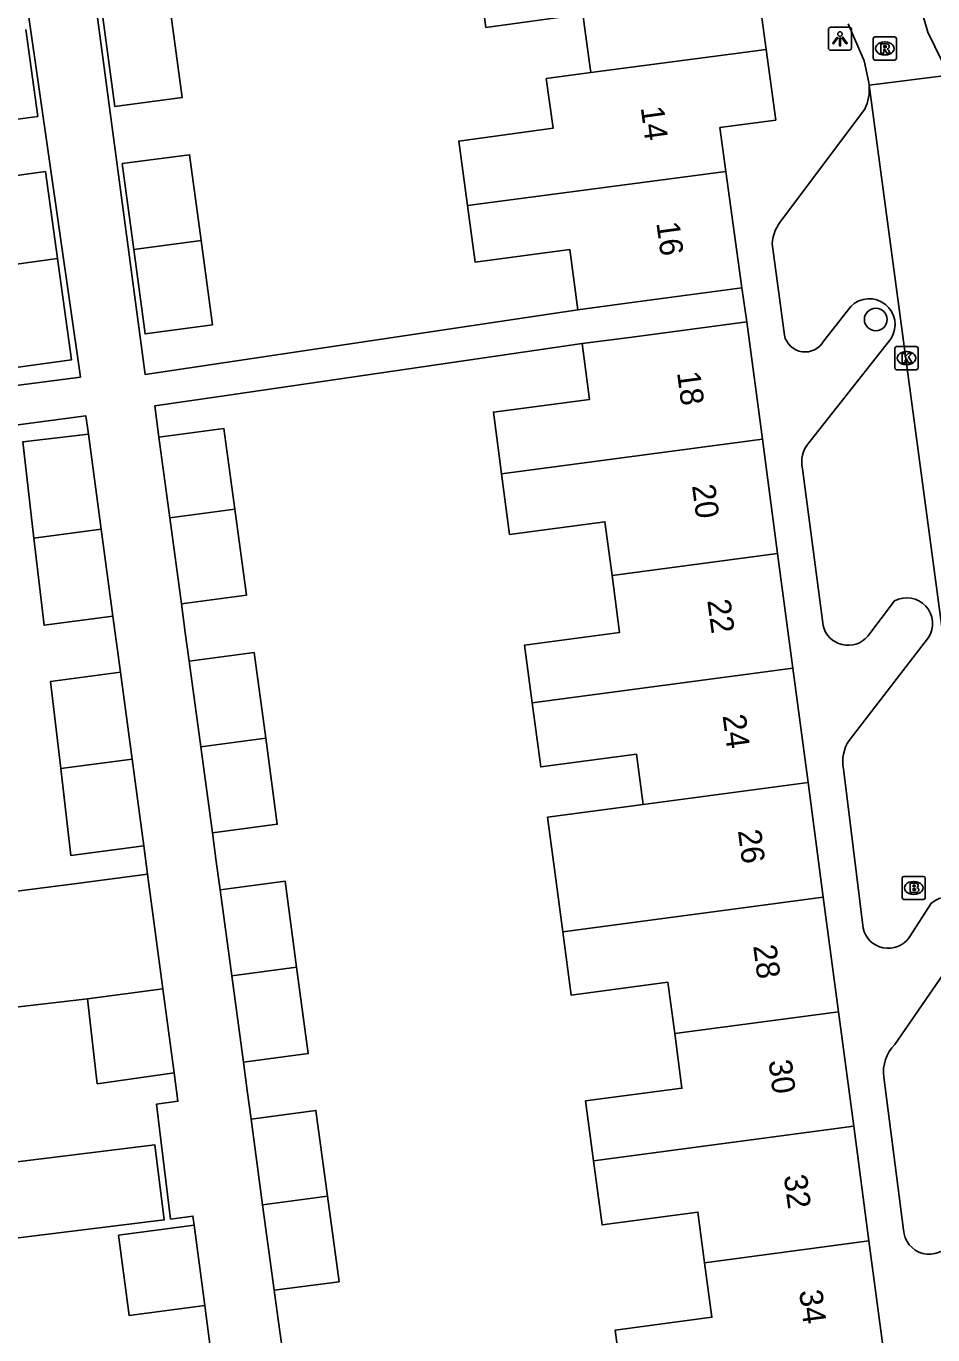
# Model space of a CAD drawing. Extents: x 163150 to 163546, y 380933 to 381635.
# Drawn here: x 163292.5 to 163331.7, y 381373.6 to 381430.1 of the extents above; entities that cross this region are included whole.
import ezdxf

# ---------------------------------------------------------------- set-up
doc = ezdxf.new("R2010")
doc.units = 0
for name, color, linetype in [('IMGEO_Boom', 7, 'Continuous'), ('IMGEO_Brandkraan', 7, 'Continuous'), ('IMGEO_Kolk', 7, 'Continuous'), ('IMGEO_Lichtpunt', 7, 'Continuous'), ('IMGEO_Pand', 7, 'Continuous'), ('IMGEO_Pand_nummerreeks', 7, 'Continuous'), ('IMGEO_Rijbaan_lokaal_open', 7, 'Continuous'), ('IMGEO_Rioolput', 7, 'Continuous'), ('IMGEO_Voetpad_open', 7, 'Continuous')]:
    doc.layers.add(name, color=color, linetype=linetype)

msp = doc.modelspace()

# ---------------------------------------------------------------- linework, layer by layer
at = {"layer": 'IMGEO_Boom'}
msp.add_circle((163329.187, 381417.469), 0.489, dxfattribs=at)
at = {"layer": 'IMGEO_Brandkraan'}
for p, q in [((163330.327, 381392.479), (163330.327, 381393.331)), ((163330.402, 381393.405), (163331.254, 381393.405)), ((163330.815, 381393.185), (163330.84, 381393.185)), ((163331.328, 381393.331), (163331.328, 381392.479)), ((163330.838, 381392.625), (163330.813, 381392.625)), ((163331.254, 381392.405), (163330.402, 381392.405))]:
    msp.add_line(p, q, dxfattribs=at)
for points in [[(163330.327, 381392.479), (163330.327, 381393.331)], [(163330.402, 381393.405), (163331.254, 381393.405)], [(163331.328, 381393.331), (163331.328, 381392.479)], [(163330.675, 381393.105), (163330.675, 381392.705), (163330.888, 381392.705)], [(163330.906, 381393.105), (163330.675, 381393.105)], [(163330.854, 381393.024), (163330.8, 381393.024), (163330.8, 381392.948)], [(163330.8, 381392.948), (163330.853, 381392.948)], [(163330.862, 381392.872), (163330.8, 381392.872), (163330.8, 381392.791)], [(163330.8, 381392.791), (163330.862, 381392.791)], [(163331.254, 381392.405), (163330.402, 381392.405)]]:
    msp.add_lwpolyline(points, dxfattribs=at)
for centre, radius, start, end in [((163330.404, 381393.329), 0.0765, 91.552, 178.448), ((163330.404, 381393.329), 0.0765, 91.552, 178.448), ((163331.252, 381393.329), 0.0765, 1.552, 88.448), ((163331.252, 381393.329), 0.0765, 1.552, 88.448), ((163330.855, 381392.986), 0.0379, 267.8285, 90.9355), ((163330.863, 381392.831), 0.0404, 269.8759, 90.5077), ((163330.894, 381392.956), 0.251, 268.6676, 293.5347), ((163330.91, 381392.96), 0.145, 59.4692, 91.5367), ((163330.935, 381393.007), 0.0922, 285.5137, 58.1501), ((163330.94, 381392.815), 0.105, 301.3115, 78.989), ((163330.404, 381392.481), 0.0765, 181.552, 268.448), ((163330.404, 381392.481), 0.0765, 181.552, 268.448), ((163331.252, 381392.481), 0.0765, 271.552, 358.448), ((163331.252, 381392.481), 0.0765, 271.552, 358.448)]:
    msp.add_arc(centre, radius, start, end, dxfattribs=at)
for centre, major_axis, ratio, start_param, end_param in [((163330.814, 381392.905), (-0.387, 0.002), 0.722429, 4.712389, 7.853982), ((163330.839, 381392.905), (-0.39, 0.002), 0.717154, 1.570796, 4.712389)]:
    msp.add_ellipse(centre, major_axis=major_axis, ratio=ratio, start_param=start_param, end_param=end_param, dxfattribs=at)
at = {"layer": 'IMGEO_Kolk'}
for p, q in [((163330.012, 381415.373), (163330.012, 381416.225)), ((163330.087, 381416.299), (163330.939, 381416.299)), ((163330.5, 381416.079), (163330.525, 381416.079)), ((163331.013, 381416.225), (163331.013, 381415.373)), ((163330.939, 381415.299), (163330.087, 381415.299)), ((163330.523, 381415.519), (163330.498, 381415.519))]:
    msp.add_line(p, q, dxfattribs=at)
for points in [[(163330.012, 381415.373), (163330.012, 381416.225)], [(163330.087, 381416.299), (163330.939, 381416.299)], [(163330.333, 381415.999), (163330.456, 381415.999), (163330.456, 381415.848), (163330.586, 381415.999), (163330.75, 381415.999), (163330.604, 381415.848), (163330.757, 381415.599), (163330.605, 381415.599), (163330.52, 381415.763), (163330.456, 381415.696), (163330.456, 381415.599), (163330.333, 381415.599), (163330.333, 381415.999)], [(163331.013, 381416.225), (163331.013, 381415.373)], [(163330.939, 381415.299), (163330.087, 381415.299)]]:
    msp.add_lwpolyline(points, dxfattribs=at)
for centre, start, end in [((163330.089, 381416.223), 91.552, 178.448), ((163330.089, 381416.223), 91.552, 178.448), ((163330.937, 381416.223), 1.552, 88.448), ((163330.937, 381416.223), 1.552, 88.448), ((163330.089, 381415.375), 181.552, 268.448), ((163330.089, 381415.375), 181.552, 268.448), ((163330.937, 381415.375), 271.552, 358.448), ((163330.937, 381415.375), 271.552, 358.448)]:
    msp.add_arc(centre, 0.0765, start, end, dxfattribs=at)
for centre, major_axis, ratio, start_param, end_param in [((163330.499, 381415.799), (-0.387, 0.002), 0.722429, 4.712389, 7.853982), ((163330.524, 381415.799), (-0.39, 0.002), 0.717154, 1.570796, 4.712389)]:
    msp.add_ellipse(centre, major_axis=major_axis, ratio=ratio, start_param=start_param, end_param=end_param, dxfattribs=at)
at = {"layer": 'IMGEO_Lichtpunt'}
for p, q in [((163327.143, 381430.005), (163327.143, 381429.198)), ((163327.143, 381430.005), (163327.143, 381429.198)), ((163328.045, 381430.1), (163327.237, 381430.1)), ((163328.045, 381430.1), (163327.237, 381430.1)), ((163328.139, 381429.198), (163328.139, 381430.005)), ((163328.139, 381429.198), (163328.139, 381430.005)), ((163327.237, 381429.104), (163328.045, 381429.104)), ((163327.237, 381429.104), (163328.045, 381429.104))]:
    msp.add_line(p, q, dxfattribs=at)
for points in [[(163327.517, 381429.669), (163327.556, 381429.641), (163327.368, 381429.379), (163327.33, 381429.406), (163327.517, 381429.669)], [(163327.619, 381429.621), (163327.666, 381429.621), (163327.666, 381429.299), (163327.619, 381429.299), (163327.619, 381429.621)], [(163327.729, 381429.641), (163327.767, 381429.668), (163327.954, 381429.406), (163327.915, 381429.378), (163327.729, 381429.641)]]:
    msp.add_lwpolyline(points, dxfattribs=at)
msp.add_circle((163327.642, 381429.803), 0.0994, dxfattribs=at)
for centre, start, end in [((163327.237, 381430.005), 90, 180), ((163327.237, 381430.005), 90, 180), ((163328.045, 381430.005), 0, 90), ((163328.045, 381430.005), 0, 90), ((163327.237, 381429.198), 180, 270), ((163327.237, 381429.198), 180, 270), ((163328.045, 381429.198), 270, 0), ((163328.045, 381429.198), 270, 360)]:
    msp.add_arc(centre, 0.0946, start, end, dxfattribs=at)
at = {"layer": 'IMGEO_Pand'}
for points in [[(163323.127, 381433.996), (163323.367, 381432.223), (163324.023, 381432.311), (163324.454, 381429.13)], [(163312.009, 381432.581), (163312.347, 381430.092), (163316.542, 381430.661), (163316.829, 381428.551), (163316.886, 381428.134)], [(163298.713, 381430.889), (163299.224, 381427.054), (163296.316, 381426.672), (163295.803, 381430.518)], [(163289.655, 381429.619), (163290.173, 381425.863), (163292.997, 381426.244), (163292.479, 381430)], [(163316.886, 381428.134), (163324.454, 381429.13)], [(163324.454, 381429.13), (163324.867, 381426.088), (163322.459, 381425.762), (163322.717, 381423.862)], [(163316.886, 381428.134), (163314.955, 381427.88), (163315.247, 381425.73), (163311.175, 381425.177), (163311.553, 381422.392)], [(163300.047, 381420.877), (163299.552, 381424.59), (163296.644, 381424.208), (163297.139, 381420.494)], [(163291.021, 381419.716), (163290.502, 381423.477), (163293.326, 381423.858), (163293.846, 381420.097)], [(163311.553, 381422.392), (163322.717, 381423.862)], [(163322.717, 381423.862), (163323.397, 381418.843)], [(163316.325, 381417.883), (163315.971, 381420.496), (163311.886, 381419.942), (163311.553, 381422.392)], [(163300.047, 381420.877), (163297.139, 381420.494)], [(163297.139, 381420.494), (163297.625, 381416.847), (163300.533, 381417.235), (163300.047, 381420.877)], [(163293.846, 381420.097), (163291.021, 381419.716)], [(163291.021, 381419.716), (163291.626, 381415.334), (163294.449, 381415.724), (163293.846, 381420.097)], [(163323.397, 381418.843), (163318.443, 381418.171), (163316.325, 381417.883)], [(163316.502, 381416.425), (163318.662, 381416.71), (163323.618, 381417.368)], [(163323.618, 381417.368), (163324.291, 381412.301)], [(163313.026, 381410.803), (163312.672, 381413.465), (163316.822, 381414.017), (163316.502, 381416.425)], [(163295.179, 381412.508), (163292.346, 381412.178), (163292.828, 381408.021)], [(163295.73, 381408.405), (163295.179, 381412.508)], [(163298.225, 381412.382), (163301.029, 381412.761), (163301.5, 381409.27)], [(163298.225, 381412.382), (163298.695, 381408.897)], [(163324.291, 381412.301), (163313.026, 381410.803)], [(163324.291, 381412.301), (163324.949, 381407.352)], [(163317.797, 381406.4), (163317.488, 381408.727), (163313.374, 381408.181), (163313.026, 381410.803)], [(163298.695, 381408.897), (163301.5, 381409.27)], [(163301.5, 381409.27), (163302.001, 381405.561), (163299.196, 381405.187)], [(163298.695, 381408.897), (163299.196, 381405.187)], [(163292.828, 381408.021), (163295.73, 381408.405)], [(163292.828, 381408.021), (163293.265, 381404.253), (163296.235, 381404.647)], [(163295.73, 381408.405), (163296.235, 381404.647)], [(163317.797, 381406.4), (163324.949, 381407.352)], [(163324.949, 381407.352), (163325.606, 381402.403)], [(163314.349, 381400.905), (163314.018, 381403.399), (163318.124, 381403.944), (163317.797, 381406.4)], [(163299.531, 381402.708), (163302.335, 381403.082), (163302.836, 381399.373)], [(163296.56, 381402.227), (163293.546, 381401.828), (163293.983, 381398.064)], [(163296.56, 381402.227), (163297.064, 381398.471)], [(163300.032, 381399), (163299.531, 381402.708)], [(163314.349, 381400.905), (163325.606, 381402.403)], [(163325.606, 381402.403), (163326.264, 381397.454)], [(163319.146, 381396.507), (163318.857, 381398.682), (163314.717, 381398.132), (163314.349, 381400.905)], [(163302.836, 381399.373), (163300.032, 381399)], [(163300.032, 381399), (163300.534, 381395.282)], [(163302.836, 381399.373), (163303.339, 381395.655), (163300.534, 381395.282)], [(163297.064, 381398.471), (163293.983, 381398.064)], [(163297.567, 381394.729), (163297.064, 381398.471)], [(163293.983, 381398.064), (163294.418, 381394.312), (163297.567, 381394.729)], [(163326.264, 381397.454), (163319.146, 381396.507)], [(163326.264, 381397.454), (163326.921, 381392.505)], [(163315.665, 381391.008), (163315.335, 381393.496), (163315.008, 381395.956), (163319.146, 381396.507)], [(163297.731, 381393.505), (163294.56, 381393.085), (163289.04, 381392.382), (163289.793, 381387.487), (163295.137, 381388.107)], [(163298.398, 381388.538), (163297.731, 381393.505)], [(163304.172, 381389.48), (163303.672, 381393.192), (163300.867, 381392.819)], [(163300.867, 381392.819), (163301.368, 381389.107)], [(163315.665, 381391.008), (163326.921, 381392.505)], [(163326.921, 381392.505), (163327.579, 381387.554)], [(163320.505, 381386.613), (163320.21, 381388.832), (163316.028, 381388.276), (163315.665, 381391.008)], [(163301.368, 381389.107), (163304.172, 381389.48)], [(163304.172, 381389.48), (163304.677, 381385.745), (163301.872, 381385.372)], [(163301.872, 381385.372), (163301.368, 381389.107)], [(163298.398, 381388.538), (163295.137, 381388.107)], [(163295.137, 381388.107), (163295.562, 381384.441), (163298.885, 381384.913)], [(163298.885, 381384.913), (163298.398, 381388.538)], [(163320.505, 381386.613), (163327.579, 381387.554)], [(163327.579, 381387.554), (163328.236, 381382.606)], [(163316.997, 381381.11), (163316.653, 381383.699), (163320.818, 381384.252), (163320.505, 381386.613)], [(163302.204, 381382.915), (163305.008, 381383.288), (163305.509, 381379.581)], [(163302.705, 381379.208), (163302.204, 381382.915)], [(163328.236, 381382.606), (163316.997, 381381.11)], [(163328.236, 381382.606), (163328.894, 381377.656)], [(163289.013, 381380.032), (163288.934, 381380.676), (163298.051, 381381.801), (163298.452, 381378.559), (163289.334, 381377.434)], [(163321.796, 381376.712), (163321.506, 381378.895), (163317.364, 381378.345), (163316.997, 381381.11)], [(163305.509, 381379.581), (163302.705, 381379.208)], [(163303.203, 381375.518), (163302.705, 381379.208)], [(163305.509, 381379.581), (163306.007, 381375.891), (163303.203, 381375.518)], [(163299.746, 381378.332), (163296.481, 381377.9), (163296.941, 381374.427), (163300.205, 381374.859)], [(163299.746, 381378.332), (163300.205, 381374.859)], [(163321.796, 381376.712), (163328.894, 381377.656)], [(163328.894, 381377.656), (163329.551, 381372.707)], [(163318.281, 381371.208), (163317.936, 381373.801), (163322.109, 381374.355), (163321.796, 381376.712)]]:
    msp.add_lwpolyline(points, dxfattribs=at)
at = {"layer": 'IMGEO_Rijbaan_lokaal_open'}
for points in [[(163331.211, 381430.682), (163331.438, 381429.883), (163332.34, 381428.031)], [(163328.901, 381427.589), (163328.886, 381427.703), (163328.69, 381428.651), (163327.996, 381430.242)], [(163332.34, 381428.031), (163328.901, 381427.589)], [(163337.636, 381362.402), (163328.901, 381427.589)]]:
    msp.add_lwpolyline(points, dxfattribs=at)
at = {"layer": 'IMGEO_Rioolput'}
for p, q in [((163329.076, 381428.754), (163329.076, 381429.606)), ((163329.151, 381429.68), (163330.003, 381429.68)), ((163329.564, 381429.46), (163329.589, 381429.46)), ((163330.077, 381429.606), (163330.077, 381428.754)), ((163329.587, 381428.9), (163329.562, 381428.9)), ((163330.003, 381428.68), (163329.151, 381428.68))]:
    msp.add_line(p, q, dxfattribs=at)
for points in [[(163329.076, 381428.754), (163329.076, 381429.606)], [(163329.151, 381429.68), (163330.003, 381429.68)], [(163329.665, 381429.378), (163329.413, 381429.38), (163329.413, 381428.98)], [(163330.077, 381429.606), (163330.077, 381428.754)], [(163329.413, 381428.98), (163329.537, 381428.98), (163329.537, 381429.142), (163329.548, 381429.142)], [(163329.591, 381429.299), (163329.537, 381429.299), (163329.537, 381429.218)], [(163329.537, 381429.218), (163329.589, 381429.218)], [(163329.595, 381429.113), (163329.666, 381428.98), (163329.806, 381428.98), (163329.741, 381429.106)], [(163330.003, 381428.68), (163329.151, 381428.68)]]:
    msp.add_lwpolyline(points, dxfattribs=at)
for centre, radius, start, end in [((163329.153, 381429.604), 0.0765, 91.552, 178.448), ((163329.153, 381429.604), 0.0765, 91.552, 178.448), ((163329.664, 381429.268), 0.109, 350.3612, 89.416), ((163330.001, 381429.604), 0.0765, 1.552, 88.448), ((163330.001, 381429.604), 0.0765, 1.552, 88.448), ((163329.547, 381429.089), 0.0533, 26.0293, 88.6989), ((163329.573, 381429.407), 0.19, 274.7715, 282.9687), ((163329.597, 381429.203), 0.0964, 77.0061, 93.1865), ((163329.611, 381429.26), 0.0378, 276.6634, 79.6772), ((163329.662, 381429.268), 0.112, 277.5842, 350.9817), ((163329.646, 381429.053), 0.108, 29.5134, 73.7905), ((163329.153, 381428.756), 0.0765, 181.552, 268.448), ((163329.153, 381428.756), 0.0765, 181.552, 268.448), ((163330.001, 381428.756), 0.0765, 271.552, 358.448), ((163330.001, 381428.756), 0.0765, 271.552, 358.448)]:
    msp.add_arc(centre, radius, start, end, dxfattribs=at)
for centre, major_axis, ratio, start_param, end_param in [((163329.563, 381429.18), (-0.387, 0.002), 0.722429, 4.712389, 7.853982), ((163329.588, 381429.18), (-0.39, 0.002), 0.717154, 1.570796, 4.712389)]:
    msp.add_ellipse(centre, major_axis=major_axis, ratio=ratio, start_param=start_param, end_param=end_param, dxfattribs=at)
at = {"layer": 'IMGEO_Voetpad_open'}
for points in [[(163316.325, 381417.883), (163297.626, 381415.095), (163292.28, 381455.215), (163295.412, 381455.658), (163310.949, 381457.733)], [(163291.235, 381439.976), (163294.836, 381414.98), (163291.731, 381414.576), (163275.971, 381412.525)], [(163325.16, 381421.816), (163328.711, 381426.55)], [(163325.24, 381416.788), (163324.711, 381420.739)], [(163323.397, 381418.843), (163323.618, 381417.368)], [(163328.115, 381418.032), (163326.94, 381416.539)], [(163316.502, 381416.425), (163300.842, 381414.143), (163298.042, 381413.735), (163298.225, 381412.382)], [(163326.299, 381412.136), (163329.849, 381416.653)], [(163276.18, 381410.802), (163295.073, 381413.303), (163295.179, 381412.508)], [(163326.912, 381404.248), (163326.027, 381411.02)], [(163299.196, 381405.187), (163299.364, 381403.946), (163299.531, 381402.708)], [(163330.002, 381405.314), (163328.84, 381403.783)], [(163296.235, 381404.647), (163296.56, 381402.227)], [(163328.046, 381399.279), (163331.468, 381403.721)], [(163328.645, 381391.163), (163327.799, 381398.048)], [(163300.534, 381395.282), (163300.7, 381394.053), (163300.867, 381392.819)], [(163297.567, 381394.729), (163297.731, 381393.505)], [(163331.596, 381392.254), (163330.637, 381390.76)], [(163330.007, 381386.141), (163333.266, 381390.863)], [(163301.872, 381385.372), (163302.036, 381384.156), (163302.204, 381382.915)], [(163298.885, 381384.913), (163299.049, 381383.688), (163298.117, 381383.555), (163298.729, 381378.593), (163299.694, 381378.722), (163299.746, 381378.332)], [(163330.391, 381378.128), (163329.531, 381384.734)], [(163303.203, 381375.518), (163303.373, 381374.262), (163303.542, 381373.013)], [(163300.205, 381374.859), (163300.367, 381373.634), (163300.525, 381372.437)]]:
    msp.add_lwpolyline(points, dxfattribs=at)
for centre, radius, start, end in [((163326.943, 381427.41), 1.966, 334.0524, 5.2215), ((163326.51, 381420.621), 1.802, 138.4821, 176.2555), ((163328.91, 381417.251), 1.114, 327.5064, 135.5052), ((163326.137, 381416.982), 0.917, 192.1867, 331.1475), ((163327.213, 381411.322), 1.224, 138.3212, 194.2837), ((163330.52, 381404.32), 1.121, 327.7232, 117.522), ((163327.992, 381404.496), 1.108, 192.9411, 319.9393), ((163329.297, 381398.388), 1.536, 144.5308, 192.7778), ((163332.303, 381391.405), 1.105, 330.5961, 129.8197), ((163329.731, 381391.407), 1.113, 192.6625, 324.4633), ((163331.265, 381384.931), 1.746, 136.1296, 186.4881), ((163331.499, 381378.186), 1.11, 182.9822, 327.2878)]:
    msp.add_arc(centre, radius, start, end, dxfattribs=at)

# ---------------------------------------------------------------- texts
at = {"layer": 'IMGEO_Pand_nummerreeks'}
for s, rotation, p in [('14', 277.7233, (163319.032, 381426.626)), ('16', 277.7204, (163319.708, 381421.64)), ('18', 277.5673, (163320.601, 381415.176)), ('20', 277.5673, (163321.249, 381410.293)), ('22', 277.5673, (163321.91, 381405.327)), ('24', 277.5673, (163322.57, 381400.351)), ('26', 277.5673, (163323.231, 381395.378)), ('28', 277.5673, (163323.892, 381390.403)), ('30', 277.5673, (163324.552, 381385.43)), ('32', 277.5673, (163325.213, 381380.464)), ('34', 277.5673, (163325.873, 381375.488))]:
    msp.add_text(s, height=1, rotation=rotation, dxfattribs=at).set_placement(p)

doc.saveas('drawing.dxf')
